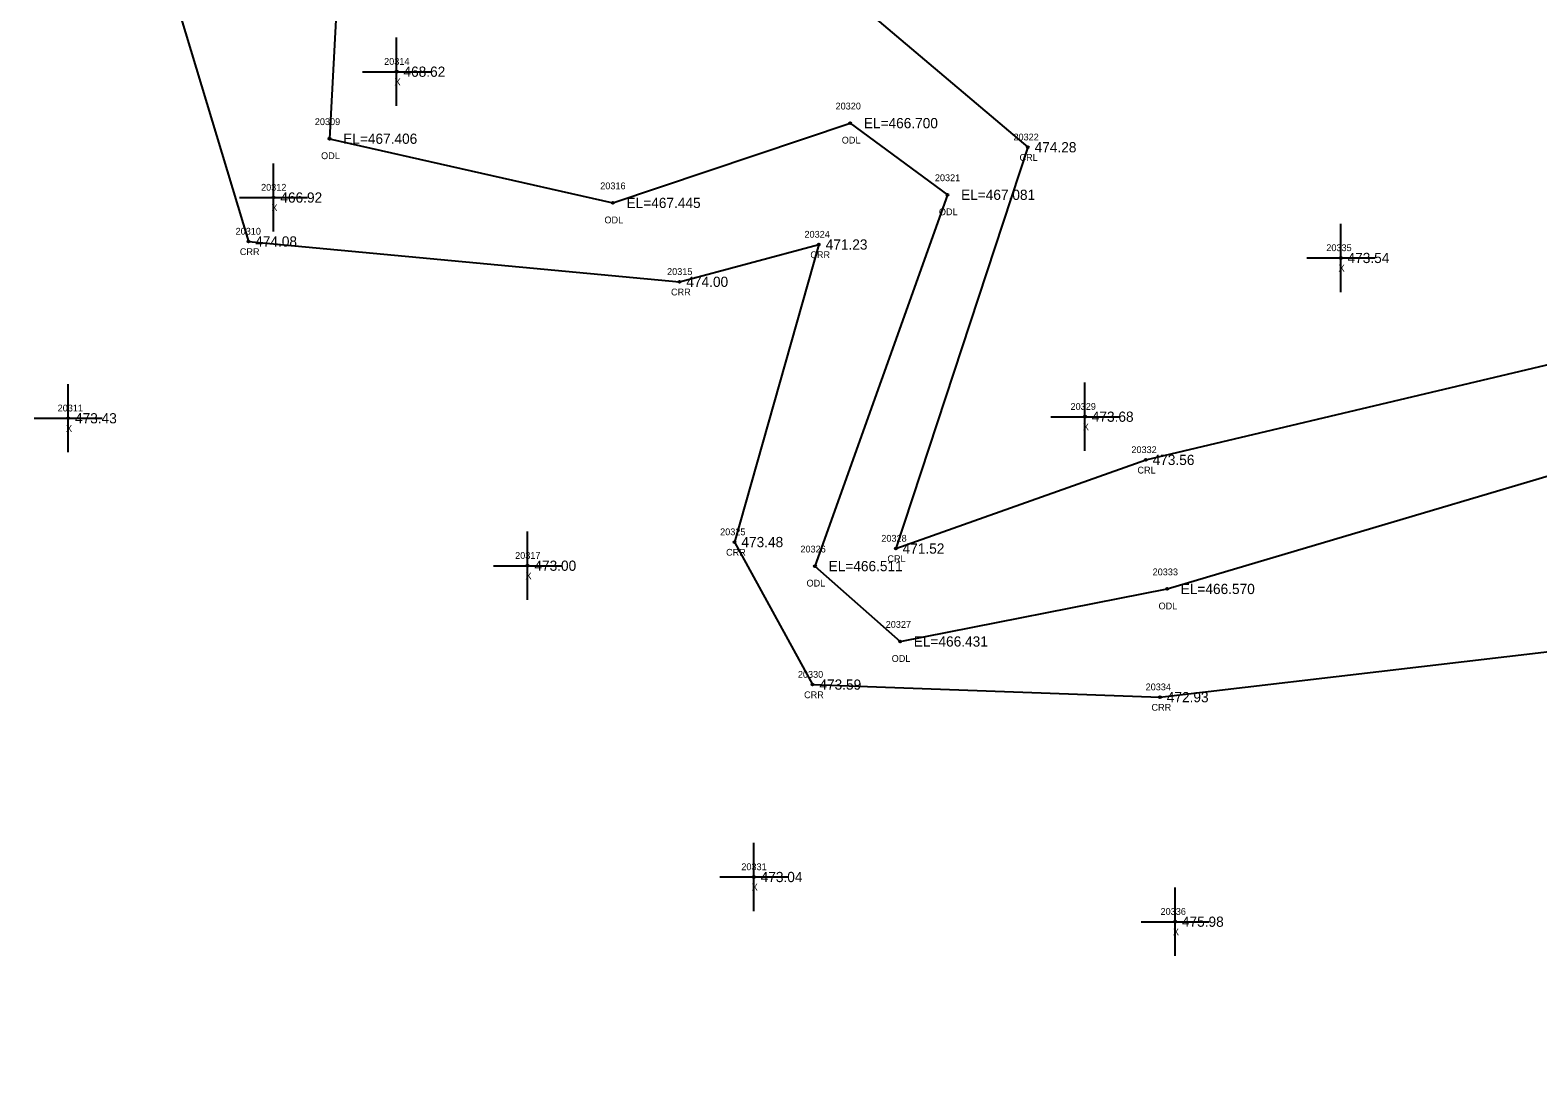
# Model space of a CAD drawing. Extents: x 1789565 to 1790548, y 909019 to 910194.
# Drawn here: x 1790081.8 to 1790303.1, y 909309.4 to 909461.5 of the extents above; entities that cross this region are included whole.
import ezdxf

# ---------------------------------------------------------------- set-up
doc = ezdxf.new("R2010")
doc.units = 0
for name, color, linetype in [('RD_EX_H2O', 7, 'Continuous'), ('RD_EX_H2O_txCode', 7, 'Continuous'), ('RD_EX_Misc', 7, 'Continuous'), ('RD_EX_Misc_txCode', 7, 'Continuous'), ('RD_EX_TX_H2O_ELEV', 7, 'Continuous'), ('RD_EX_TX_Misc_ELEV', 7, 'Continuous'), ('RD_SMD_Locator', 7, 'Continuous')]:
    doc.layers.add(name, color=color, linetype=linetype)

msp = doc.modelspace()

# ---------------------------------------------------------------- linework, layer by layer
at = {"layer": 'RD_EX_H2O'}
for points in [[(1789926.75, 910151.78), (1789921.87, 910061.22), (1789923.33, 910015.8), (1789922.65, 909953.15), (1789957.79, 909859.65), (1789976.3, 909811.78), (1790009.05, 909737.59), (1790033.3, 909656.58), (1790043.84, 909640.77), (1790040.94, 909620.44), (1790068.41, 909598.88), (1790105.46, 909552.21), (1790128.28, 909493.4), (1790125.72, 909445.59), (1790167.31, 909436.17), (1790202.14, 909447.88), (1790216.41, 909437.36), (1790196.97, 909382.86), (1790209.47, 909371.8), (1790248.65, 909379.51), (1790333.47, 909404.65), (1790412.72, 909370.84), (1790438.82, 909377.48), (1790480.23, 909327.32)], [(1789942.19, 910149.47), (1789928.94, 910061.47), (1789937.03, 910016.56), (1789929.09, 909954.8), (1789962.46, 909861.74), (1789984.97, 909814.65), (1790017.82, 909740.15), (1790045.4, 909660.05), (1790055.69, 909646.96), (1790055.38, 909644.82), (1790053.69, 909634.91), (1790054.91, 909627.64), (1790075.55, 909607.72), (1790122.18, 909568.31), (1790142.55, 909490.86), (1790145.56, 909467.27), (1790204.21, 909464.64), (1790228.21, 909444.34), (1790208.83, 909385.44), (1790245.53, 909398.45), (1790340.56, 909420.98), (1790422.56, 909390.06), (1790444.95, 909390.88), (1790496, 909329.5)], [(1790030.97, 909616.21), (1790039.23, 909609.17), (1790060.86, 909590.41), (1790089.09, 909540.87), (1790093.77, 909497), (1790113.81, 909430.51), (1790177.09, 909424.59), (1790197.54, 909430.06), (1790185.17, 909386.39), (1790196.62, 909365.47), (1790247.61, 909363.63), (1790324.38, 909372.65), (1790407.18, 909352.01), (1790424.72, 909347.04), (1790471.09, 909309.36)]]:
    msp.add_lwpolyline(points, dxfattribs=at)
at = {"layer": 'RD_EX_Misc'}
for p, q in [((1790135.57, 909450.43), (1790135.57, 909460.43)), ((1790130.57, 909455.43), (1790140.57, 909455.43)), ((1790117.5, 909431.96), (1790117.5, 909441.96)), ((1790112.5, 909436.96), (1790122.5, 909436.96)), ((1790274.14, 909423.09), (1790274.14, 909433.09)), ((1790269.14, 909428.09), (1790279.14, 909428.09)), ((1790087.36, 909399.56), (1790087.36, 909409.56)), ((1790236.6, 909399.79), (1790236.6, 909409.79)), ((1790082.36, 909404.56), (1790092.36, 909404.56)), ((1790231.6, 909404.79), (1790241.6, 909404.79)), ((1790154.79, 909377.92), (1790154.79, 909387.92)), ((1790149.79, 909382.92), (1790159.79, 909382.92)), ((1790188, 909332.23), (1790188, 909342.23)), ((1790183, 909337.23), (1790193, 909337.23)), ((1790249.83, 909325.67), (1790249.83, 909335.67)), ((1790244.83, 909330.67), (1790254.83, 909330.67))]:
    msp.add_line(p, q, dxfattribs=at)
at = {"layer": 'RD_SMD_Locator'}
for centre in [(1790135.57, 909455.43), (1790202.14, 909447.88), (1790125.72, 909445.59), (1790228.21, 909444.34), (1790216.41, 909437.36), (1790117.5, 909436.96), (1790167.31, 909436.17), (1790113.81, 909430.51), (1790197.54, 909430.06), (1790274.14, 909428.09), (1790177.09, 909424.59), (1790087.36, 909404.56), (1790236.6, 909404.79), (1790245.53, 909398.45), (1790185.17, 909386.39), (1790208.83, 909385.44), (1790154.79, 909382.92), (1790196.97, 909382.86), (1790248.65, 909379.51), (1790209.47, 909371.8), (1790196.62, 909365.47), (1790247.61, 909363.63), (1790188, 909337.23), (1790249.83, 909330.67)]:
    msp.add_circle(centre, 0.15, dxfattribs=at)

# ---------------------------------------------------------------- texts
at = {"layer": 'RD_EX_H2O_txCode'}
for s, p in [('20320', (1790199.99, 909449.88)), ('20309', (1790123.56, 909447.59)), ('20322', (1790226.1, 909445.34)), ('ODL', (1790200.9, 909444.88)), ('ODL', (1790124.48, 909442.59)), ('CRL', (1790226.99, 909442.34)), ('20321', (1790214.57, 909439.36)), ('20316', (1790165.45, 909438.17)), ('ODL', (1790215.16, 909434.36)), ('ODL', (1790166.07, 909433.17)), ('20310', (1790111.93, 909431.51)), ('20324', (1790195.43, 909431.06)), ('CRR', (1790112.55, 909428.51)), ('CRR', (1790196.29, 909428.06)), ('20315', (1790175.26, 909425.59)), ('CRR', (1790175.84, 909422.59)), ('20332', (1790243.41, 909399.45)), ('CRL', (1790244.3, 909396.45)), ('20325', (1790183.05, 909387.39)), ('20328', (1790206.71, 909386.44)), ('CRR', (1790183.92, 909384.39)), ('20326', (1790194.83, 909384.86)), ('CRL', (1790207.6, 909383.44)), ('20333', (1790246.53, 909381.51)), ('ODL', (1790195.73, 909379.86)), ('ODL', (1790247.4, 909376.51)), ('20327', (1790207.35, 909373.8)), ('ODL', (1790208.23, 909368.8)), ('20330', (1790194.46, 909366.47)), ('CRR', (1790195.37, 909363.47)), ('20334', (1790245.5, 909364.63)), ('CRR', (1790246.36, 909361.63))]:
    msp.add_text(s, height=1, dxfattribs=at).set_placement(p)
at = {"layer": 'RD_EX_Misc_txCode'}
for s, p in [('20314', (1790133.73, 909456.43)), ('X', (1790135.25, 909453.43)), ('20312', (1790115.67, 909437.96)), ('X', (1790117.19, 909434.96)), ('20335', (1790272.02, 909429.09)), ('X', (1790273.82, 909426.09)), ('20311', (1790085.81, 909405.56)), ('20329', (1790234.48, 909405.79)), ('X', (1790087.04, 909402.56)), ('X', (1790236.29, 909402.79)), ('20317', (1790152.96, 909383.92)), ('X', (1790154.48, 909380.92)), ('20331', (1790186.16, 909338.23)), ('X', (1790187.68, 909335.23)), ('20336', (1790247.69, 909331.67)), ('X', (1790249.51, 909328.67))]:
    msp.add_text(s, height=1, dxfattribs=at).set_placement(p)
at = {"layer": 'RD_EX_TX_H2O_ELEV'}
for s, p in [('EL=466.700', (1790204.14, 909447.13)), ('EL=467.406', (1790127.72, 909444.84)), ('474.28', (1790229.21, 909443.59)), ('EL=467.081', (1790218.41, 909436.61)), ('EL=467.445', (1790169.31, 909435.42)), ('474.08', (1790114.81, 909429.76)), ('471.23', (1790198.54, 909429.31)), ('474.00', (1790178.09, 909423.84)), ('473.56', (1790246.53, 909397.7)), ('473.48', (1790186.17, 909385.64)), ('471.52', (1790209.83, 909384.69)), ('EL=466.511', (1790198.97, 909382.11)), ('EL=466.570', (1790250.65, 909378.76)), ('EL=466.431', (1790211.47, 909371.05)), ('473.59', (1790197.62, 909364.72)), ('472.93', (1790248.61, 909362.88))]:
    msp.add_text(s, height=1.5, dxfattribs=at).set_placement(p)
at = {"layer": 'RD_EX_TX_Misc_ELEV'}
for s, p in [('468.62', (1790136.57, 909454.68)), ('466.92', (1790118.5, 909436.21)), ('473.54', (1790275.14, 909427.34)), ('473.43', (1790088.36, 909403.81)), ('473.68', (1790237.6, 909404.04)), ('473.00', (1790155.79, 909382.17)), ('473.04', (1790189, 909336.48)), ('475.98', (1790250.83, 909329.92))]:
    msp.add_text(s, height=1.5, dxfattribs=at).set_placement(p)

doc.saveas('drawing.dxf')
